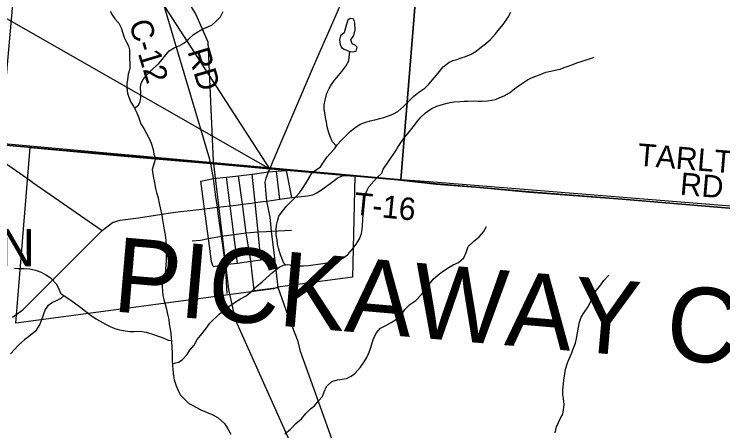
# Model space of a CAD drawing. Extents: x 0 to 42.5, y 0 to 22.
# Drawn here: x 6.916 to 7.815, y 18.353 to 18.882 of the extents above; entities that cross this region are included whole.
import ezdxf

# ---------------------------------------------------------------- set-up
doc = ezdxf.new("R2010")
doc.units = 0
for name, color, linetype in [('Default', 7, 'Continuous'), ('GM_X_City_Street', 7, 'Continuous'), ('GM_X_Corporation', 7, 'Continuous'), ('GM_X_Corporation_Text', 7, 'Continuous'), ('GM_X_County_Road', 7, 'Continuous'), ('GM_X_County_Road_Text', 7, 'Continuous'), ('GM_X_County_Text', 7, 'Continuous'), ('GM_X_Interchange_Ramps', 7, 'Continuous'), ('GM_X_Major_River', 7, 'Continuous'), ('GM_X_Minor_Lake', 7, 'Continuous'), ('GM_X_Minor_River', 7, 'Continuous'), ('GM_X_Rail_Line', 7, 'Continuous'), ('GM_X_Section', 7, 'Continuous'), ('GM_X_State_Route', 7, 'Continuous'), ('GM_X_Township', 7, 'Continuous'), ('GM_X_Township_Road', 7, 'Continuous'), ('GM_X_Township_Road_Text', 7, 'Continuous'), ('SH_Cut_Line', 7, 'Continuous')]:
    doc.layers.add(name, color=color, linetype=linetype)

msp = doc.modelspace()

# ---------------------------------------------------------------- linework, layer by layer
at = {"layer": 'Default'}
msp.add_lwpolyline([(6.77517, 18.95149), (7.23995, 18.68541), (6.77517, 19.405)], close=True, dxfattribs=at)
at = {"layer": 'GM_X_City_Street'}
for p, q in [((7.25283, 18.64698), (7.24854, 18.68262)), ((7.26806, 18.6492), (7.26126, 18.68366)), ((7.14132, 18.59393), (7.15185, 18.59509)), ((7.18585, 18.52716), (7.18372, 18.56352)), ((7.22001, 18.53092), (7.2505, 18.53493))]:
    msp.add_line(p, q, dxfattribs=at)
for points in [[(7.1707, 18.65631), (7.1687, 18.67345), (7.16507, 18.69211)], [(7.15243, 18.67005), (7.1687, 18.67345), (7.18511, 18.67508), (7.20034, 18.67671), (7.21779, 18.67878), (7.23843, 18.68183), (7.24854, 18.68262), (7.26126, 18.68366)], [(7.19892, 18.5658), (7.1943, 18.60232), (7.18971, 18.63869), (7.18511, 18.67508)], [(7.22001, 18.53092), (7.21591, 18.56814), (7.21005, 18.60448), (7.2052, 18.64053), (7.20034, 18.67671)], [(7.2288, 18.5699), (7.22521, 18.60536), (7.22144, 18.64266), (7.21779, 18.67878)], [(7.23627, 18.64461), (7.25283, 18.64698), (7.26806, 18.6492), (7.28773, 18.65113), (7.29445, 18.65246), (7.29879, 18.6545), (7.30436, 18.65786), (7.32118, 18.67025), (7.32597, 18.67421), (7.33339, 18.67733), (7.35046, 18.67616)], [(7.16816, 18.56169), (7.16581, 18.56785), (7.16199, 18.59702), (7.15703, 18.63493), (7.15243, 18.67005)], [(7.17501, 18.62543), (7.17343, 18.63677), (7.17106, 18.65319), (7.1707, 18.65631)], [(7.2505, 18.53493), (7.24638, 18.57195), (7.24234, 18.60636), (7.24026, 18.62405), (7.23627, 18.64461)], [(7.18372, 18.56352), (7.18369, 18.56404), (7.17853, 18.60016), (7.17501, 18.62543)], [(7.23592, 18.60598), (7.24234, 18.60636), (7.26765, 18.60783)], [(7.15185, 18.59509), (7.16199, 18.59702), (7.17853, 18.60016), (7.1943, 18.60232), (7.21005, 18.60448), (7.22521, 18.60536), (7.23592, 18.60598)], [(7.18645, 18.56436), (7.19892, 18.5658), (7.21591, 18.56814), (7.2288, 18.5699), (7.24638, 18.57195)], [(7.16816, 18.56169), (7.18369, 18.56404), (7.18645, 18.56436)]]:
    msp.add_lwpolyline(points, dxfattribs=at)
at = {"layer": 'GM_X_Corporation'}
msp.add_lwpolyline([(6.93599, 18.7127), (7.05994, 18.70145), (7.21478, 18.68809), (7.34783, 18.67645), (7.34506, 18.54795), (7.25039, 18.53519), (7.24478, 18.53335), (6.9177, 18.48933)], close=True, dxfattribs=at)
at = {"layer": 'GM_X_County_Road'}
msp.add_line((6.93943, 18.66839), (7.02735, 18.60733), dxfattribs=at)
for points in [[(7.16507, 18.69211), (7.16371, 18.69747), (7.15108, 18.74032), (7.12072, 18.84281), (7.0876, 18.95511)], [(6.86201, 18.71925), (6.87353, 18.71414), (6.93663, 18.67033), (6.93943, 18.66839)], [(7.3211, 18.33541), (7.29585, 18.40643), (7.27902, 18.4534), (7.27596, 18.46637), (7.2633, 18.49884), (7.2505, 18.53493)]]:
    msp.add_lwpolyline(points, dxfattribs=at)
at = {"layer": 'GM_X_Interchange_Ramps'}
msp.add_lwpolyline([(6.42536, 18.76104), (6.65154, 18.73968), (6.84834, 18.72185), (6.86191, 18.71951), (7.16496, 18.69237), (7.23984, 18.68568), (7.26115, 18.68392), (7.33328, 18.6776), (7.35035, 18.67643), (7.40226, 18.67187), (7.45109, 18.6665), (7.50672, 18.66195), (7.56903, 18.65618), (7.68737, 18.6472), (7.92905, 18.62689)], dxfattribs=at)
at = {"layer": 'GM_X_Major_River'}
for points in [[(7.0375, 18.88604), (7.03993, 18.88128), (7.04351, 18.87633), (7.04821, 18.87061), (7.05121, 18.86452), (7.05402, 18.85672), (7.05569, 18.85139), (7.05832, 18.84663), (7.06076, 18.84187), (7.06206, 18.83693), (7.06183, 18.83029), (7.062, 18.82554), (7.06234, 18.81946), (7.06231, 18.81243), (7.06038, 18.80579), (7.0592, 18.79877), (7.05842, 18.79403), (7.05858, 18.78814), (7.0593, 18.78168), (7.06117, 18.77673), (7.0636, 18.77045), (7.06754, 18.76417), (7.0713, 18.75693), (7.07372, 18.75046), (7.07634, 18.74286), (7.0801, 18.73676), (7.08366, 18.73067), (7.08647, 18.72477), (7.08947, 18.7183), (7.09208, 18.71031), (7.093, 18.70442), (7.09478, 18.69861)], [(7.09475, 18.69889), (7.09083, 18.68476), (7.09158, 18.67944), (7.09234, 18.67392), (7.09347, 18.66783), (7.09499, 18.66042), (7.09631, 18.65547), (7.09821, 18.64862), (7.09916, 18.64386), (7.10067, 18.63606), (7.10276, 18.62693), (7.1037, 18.62084), (7.10445, 18.61552), (7.10597, 18.60791), (7.1071, 18.60163), (7.10785, 18.5946), (7.10841, 18.58624), (7.10878, 18.58054), (7.10857, 18.57484), (7.10837, 18.56876), (7.10798, 18.56345), (7.10758, 18.55851), (7.107, 18.55225), (7.10545, 18.54656), (7.10391, 18.54144), (7.10352, 18.53594), (7.1037, 18.53024), (7.10426, 18.52472), (7.1054, 18.51978), (7.1073, 18.51387), (7.10881, 18.50741), (7.11033, 18.50094), (7.11165, 18.49428), (7.11241, 18.48857), (7.11354, 18.48192), (7.11429, 18.47659), (7.11466, 18.47146), (7.11523, 18.46614), (7.11579, 18.45949), (7.11615, 18.45132), (7.11613, 18.44258), (7.1165, 18.43574), (7.11706, 18.43061), (7.11781, 18.42243), (7.11876, 18.41749), (7.12104, 18.41006), (7.12389, 18.40415), (7.12675, 18.39786), (7.1319, 18.39289), (7.13725, 18.38753), (7.14221, 18.38503), (7.15253, 18.37963), (7.15769, 18.3775), (7.16763, 18.37306), (7.1745, 18.3694), (7.18233, 18.36213), (7.18671, 18.35526), (7.19052, 18.34839)]]:
    msp.add_lwpolyline(points, dxfattribs=at)
at = {"layer": 'GM_X_Minor_Lake'}
for points in [[(7.34036, 18.83512), (7.34471, 18.83431), (7.34965, 18.8352), (7.35084, 18.84013), (7.34859, 18.84244), (7.34444, 18.84419), (7.34299, 18.84953), (7.34665, 18.855), (7.34825, 18.8622), (7.34778, 18.87057), (7.34652, 18.87571), (7.34178, 18.87653), (7.33911, 18.87466), (7.33675, 18.86765), (7.33456, 18.85855), (7.32977, 18.85442), (7.32839, 18.8495), (7.32927, 18.8436), (7.33112, 18.83959), (7.33432, 18.83765)], [(7.33432, 18.83765), (7.34036, 18.83512)]]:
    msp.add_lwpolyline(points, dxfattribs=at)
at = {"layer": 'GM_X_Minor_River'}
for points in [[(7.06838, 18.76255), (7.07318, 18.76641), (7.07551, 18.77132), (7.07652, 18.77625), (7.0764, 18.78271), (7.07609, 18.78823), (7.07634, 18.79374), (7.07944, 18.79921), (7.08464, 18.806), (7.09135, 18.81257), (7.09882, 18.81914), (7.10343, 18.8246), (7.10824, 18.83044), (7.11247, 18.83533), (7.11877, 18.83945), (7.12487, 18.84166), (7.13097, 18.8452), (7.13672, 18.85046), (7.14304, 18.85609), (7.14877, 18.85964), (7.15545, 18.86356), (7.16155, 18.86596), (7.1667, 18.86837), (7.17168, 18.87269), (7.17762, 18.8787), (7.18092, 18.88532)], [(7.29355, 18.6811), (7.30414, 18.68825), (7.30915, 18.69522), (7.31263, 18.7007), (7.31686, 18.70559), (7.32204, 18.71085), (7.32609, 18.7167), (7.3305, 18.72178), (7.33626, 18.72723), (7.3424, 18.73362), (7.34794, 18.73774), (7.35482, 18.74223), (7.36187, 18.74481), (7.36719, 18.74646), (7.37309, 18.74792), (7.37974, 18.74956), (7.3845, 18.75083), (7.39078, 18.75285), (7.39592, 18.75489), (7.4026, 18.75843), (7.41007, 18.765), (7.41659, 18.77138), (7.42292, 18.77778), (7.42924, 18.78303), (7.43688, 18.78826), (7.44186, 18.79296), (7.44917, 18.80162), (7.45379, 18.80727), (7.46013, 18.81499), (7.46722, 18.8208), (7.47217, 18.82303), (7.47731, 18.82468), (7.48283, 18.82671), (7.48835, 18.82836), (7.49559, 18.83133), (7.5017, 18.83506), (7.50859, 18.84049), (7.51356, 18.84443), (7.52026, 18.84987), (7.52641, 18.85721), (7.5316, 18.86342), (7.53603, 18.86908), (7.54239, 18.87813), (7.54588, 18.88455)], [(7.32454, 18.71447), (7.31949, 18.71981), (7.31653, 18.7265), (7.31488, 18.73126), (7.31288, 18.73889), (7.31182, 18.74498), (7.31074, 18.75069), (7.30968, 18.75659), (7.30879, 18.76155), (7.30885, 18.76687), (7.31024, 18.77274), (7.31243, 18.78165), (7.31553, 18.7875), (7.31844, 18.7926), (7.3221, 18.79826), (7.32729, 18.80429), (7.33152, 18.80918), (7.33653, 18.81616), (7.3404, 18.82276), (7.34163, 18.83488)], [(7.37568, 18.67408), (7.38197, 18.68017), (7.38373, 18.6851), (7.38875, 18.69245), (7.39337, 18.69867), (7.39916, 18.70735), (7.40245, 18.71301), (7.40573, 18.71811), (7.41151, 18.72603), (7.41709, 18.733), (7.42209, 18.73902), (7.42748, 18.74599), (7.43171, 18.75108), (7.43765, 18.75671), (7.44492, 18.76195), (7.45197, 18.7653), (7.4573, 18.76695), (7.46338, 18.7684), (7.46871, 18.77005), (7.47384, 18.77076), (7.48105, 18.77125), (7.48655, 18.77157), (7.49129, 18.77171), (7.49793, 18.77182), (7.50437, 18.77156), (7.50949, 18.7717), (7.51632, 18.77219), (7.52164, 18.7727), (7.52658, 18.77379), (7.53211, 18.7762), (7.53763, 18.77842), (7.54412, 18.78234), (7.55273, 18.78908), (7.55961, 18.79376), (7.56687, 18.79881), (7.57221, 18.80103), (7.57755, 18.80344), (7.58459, 18.80584), (7.59011, 18.80825), (7.59677, 18.80969), (7.60228, 18.81077), (7.60836, 18.81242), (7.61369, 18.81426), (7.61978, 18.81628), (7.62473, 18.81813), (7.62969, 18.82016), (7.63654, 18.82256), (7.64149, 18.82403), (7.64682, 18.82568), (7.65157, 18.82734)], [(7.25995, 18.56366), (7.25793, 18.56577), (7.25375, 18.57625), (7.2509, 18.58482), (7.24976, 18.58996), (7.2492, 18.59528), (7.24806, 18.60118), (7.24808, 18.60764), (7.24866, 18.61409), (7.24982, 18.61902), (7.25156, 18.62528), (7.25616, 18.63189), (7.26134, 18.63812), (7.26709, 18.64397), (7.27284, 18.65), (7.27763, 18.65529), (7.28147, 18.66077), (7.28627, 18.66795), (7.29363, 18.6811)], [(7.11638, 18.43803), (7.11918, 18.43876), (7.12397, 18.44005), (7.12895, 18.44306), (7.13508, 18.44966), (7.13854, 18.45514), (7.14391, 18.46175), (7.14794, 18.46875), (7.15216, 18.47404), (7.15868, 18.48235), (7.16386, 18.48934), (7.17613, 18.50141), (7.18168, 18.50574), (7.18819, 18.51063), (7.1949, 18.51552), (7.20275, 18.52059), (7.20984, 18.52415), (7.21769, 18.53055), (7.22306, 18.53621), (7.23034, 18.54223), (7.23551, 18.54675), (7.24337, 18.55372), (7.2518, 18.56069), (7.25755, 18.56331), (7.26252, 18.56403), (7.26845, 18.56304), (7.27533, 18.56223), (7.28279, 18.56217), (7.28929, 18.5627), (7.29503, 18.56342), (7.30116, 18.56432), (7.30747, 18.56523), (7.31723, 18.56686), (7.32259, 18.56796), (7.32737, 18.56964), (7.33254, 18.57226), (7.33848, 18.5764), (7.34461, 18.583), (7.34979, 18.5898), (7.35363, 18.5968), (7.35652, 18.60362), (7.3571, 18.60855), (7.35749, 18.61368), (7.35808, 18.62127), (7.35848, 18.62754), (7.35868, 18.63323), (7.35869, 18.63817), (7.35928, 18.64406), (7.36044, 18.65146), (7.36294, 18.65771), (7.36563, 18.66263), (7.37558, 18.67389)], [(7.259, 18.34903), (7.26628, 18.35506), (7.27299, 18.36204), (7.28008, 18.36807), (7.28583, 18.37486), (7.29177, 18.38052), (7.29656, 18.38447), (7.30212, 18.39146), (7.30673, 18.39636), (7.30884, 18.40243), (7.31192, 18.40905), (7.31882, 18.41546), (7.3259, 18.41769), (7.33202, 18.41859), (7.33719, 18.41932), (7.34312, 18.42231), (7.3481, 18.42569), (7.3552, 18.43381), (7.35961, 18.44024), (7.36325, 18.44572), (7.36595, 18.45273), (7.36806, 18.4586), (7.36999, 18.46448), (7.37153, 18.46959), (7.37499, 18.47679), (7.38036, 18.48321), (7.38706, 18.48658), (7.39395, 18.49032), (7.402, 18.49539), (7.40813, 18.50162), (7.41139, 18.50672), (7.41753, 18.51333), (7.42538, 18.5184), (7.43209, 18.52538), (7.43727, 18.53142), (7.44264, 18.53898), (7.44724, 18.54521), (7.45376, 18.55105), (7.46046, 18.55613), (7.46774, 18.56064), (7.47291, 18.56345), (7.47942, 18.56644), (7.48632, 18.57247), (7.4892, 18.5791), (7.4917, 18.58706), (7.4986, 18.59328), (7.50588, 18.5993), (7.51125, 18.60553), (7.51509, 18.61215)], [(7.11513, 18.46702), (7.1114, 18.46731), (7.1051, 18.47039), (7.09994, 18.47233), (7.0942, 18.47408), (7.08331, 18.47758), (7.0749, 18.47897), (7.06801, 18.47864), (7.06246, 18.47868), (7.05634, 18.47948), (7.04946, 18.48067), (7.04392, 18.48242), (7.0378, 18.48494), (7.03188, 18.48764), (7.025, 18.49149), (7.01965, 18.49476), (7.01259, 18.49937), (7.0059, 18.50435), (6.99998, 18.50915), (6.99216, 18.51509), (6.98604, 18.51932), (6.97535, 18.52642), (6.97173, 18.53424), (6.96945, 18.53919), (6.96277, 18.5457), (6.95627, 18.5503), (6.95016, 18.55377), (6.94443, 18.5559), (6.93563, 18.55805), (6.92817, 18.55849), (6.92052, 18.55873), (6.91555, 18.55877)], [(7.60213, 18.35015), (7.60368, 18.35792), (7.60637, 18.36322), (7.60886, 18.3689), (7.61174, 18.37401), (7.6129, 18.37951), (7.61349, 18.38615), (7.61255, 18.39395), (7.61199, 18.39889), (7.612, 18.40383), (7.61318, 18.41712), (7.61434, 18.42509), (7.61531, 18.43097), (7.61762, 18.43931), (7.61974, 18.44442), (7.62339, 18.4518), (7.62512, 18.45711), (7.628, 18.46431), (7.62936, 18.47019), (7.63033, 18.47721), (7.63187, 18.4846), (7.63323, 18.49086), (7.63534, 18.49712), (7.6388, 18.50317), (7.64379, 18.50978), (7.64705, 18.51622), (7.64974, 18.52322), (7.65416, 18.53117), (7.65895, 18.53664), (7.66394, 18.54383), (7.67008, 18.55043)], [(6.97878, 18.52414), (6.97476, 18.52073), (6.96883, 18.51792), (6.96404, 18.51587), (6.9581, 18.51173), (6.95503, 18.50681), (6.95253, 18.49961), (6.94965, 18.49242), (6.94772, 18.48749), (6.94273, 18.47936), (6.93392, 18.47202), (6.92913, 18.46863), (6.92127, 18.46147), (6.91648, 18.45638), (6.91111, 18.45072)]]:
    msp.add_lwpolyline(points, dxfattribs=at)
at = {"layer": 'GM_X_Rail_Line'}
for points in [[(6.93446, 19.48033), (6.95529, 19.40509), (7.06565, 19.02428), (7.09443, 18.96319), (7.12266, 18.92015), (7.14624, 18.88148), (7.16122, 18.84711), (7.16795, 18.69518)], [(7.16795, 18.69518), (7.18749, 18.53209), (7.19593, 18.49415), (7.38905, 18.06269), (7.41372, 18.0008), (7.43212, 17.9111), (7.47197, 17.65619), (7.56463, 17.14484), (7.58341, 17.04913), (7.60553, 16.97375), (7.61971, 16.94218), (7.74723, 16.71174), (7.7666, 16.68172), (7.79639, 16.63739), (7.93488, 16.50931), (7.97601, 16.46994), (7.98854, 16.45646), (7.99258, 16.44438), (7.9907, 16.42806), (7.98347, 16.32444), (7.94829, 15.9349)]]:
    msp.add_lwpolyline(points, dxfattribs=at)
at = {"layer": 'GM_X_Section'}
for points in [[(6.94317, 19.22409), (7.44741, 19.17728), (7.40642, 18.67181), (6.9401, 18.71384), (6.89806, 18.71772)], [(7.44741, 19.17728), (7.95504, 19.13799), (7.91366, 18.63105), (7.44206, 18.66911), (7.40642, 18.67181)]]:
    msp.add_lwpolyline(points, close=True, dxfattribs=at)
at = {"layer": 'GM_X_State_Route'}
msp.add_line((7.08698, 18.62555), (7.11096, 18.62915), dxfattribs=at)
for points in [[(7.24005, 18.68566), (7.25313, 18.71656), (7.29156, 18.80651), (7.30112, 18.82834), (7.31392, 18.85794), (7.34504, 18.92911)], [(7.23395, 18.66809), (7.2339, 18.66857), (7.23553, 18.67389), (7.23843, 18.68183)], [(7.23843, 18.68183), (7.23995, 18.68541), (7.24003, 18.68559)], [(7.23101, 18.64392), (7.23627, 18.64461), (7.23538, 18.65378), (7.23395, 18.66809)], [(7.2166, 18.64202), (7.22144, 18.64266), (7.23101, 18.64392)], [(7.13494, 18.63244), (7.15703, 18.63493), (7.17343, 18.63677), (7.18971, 18.63869), (7.19745, 18.63961)], [(7.19745, 18.63961), (7.2052, 18.64053), (7.20596, 18.64062), (7.2166, 18.64202)], [(7.11096, 18.62915), (7.12678, 18.63152), (7.13494, 18.63244)], [(6.91343, 18.49734), (6.92641, 18.5066), (7.02735, 18.60733), (7.04029, 18.61725), (7.04989, 18.62028), (7.07355, 18.62353), (7.08698, 18.62555)]]:
    msp.add_lwpolyline(points, dxfattribs=at)
at = {"layer": 'GM_X_Township'}
msp.add_lwpolyline([(6.42536, 18.76104), (6.65154, 18.73968), (6.84834, 18.72185), (6.86191, 18.71951), (7.16496, 18.69237), (7.23984, 18.68568), (7.26115, 18.68392), (7.33328, 18.6776), (7.35035, 18.67643), (7.40226, 18.67187), (7.45109, 18.6665), (7.50672, 18.66195), (7.56903, 18.65618), (7.68737, 18.6472), (7.92905, 18.62689)], dxfattribs=at)
at = {"layer": 'GM_X_Township_Road'}
msp.add_lwpolyline([(7.35046, 18.67616), (7.40237, 18.67161), (7.4512, 18.66623), (7.50683, 18.66169), (7.56914, 18.65591), (7.68748, 18.64693), (7.92916, 18.62662)], dxfattribs=at)
at = {"layer": 'SH_Cut_Line'}
for points in [[(7.92905, 18.62689), (7.68737, 18.6472), (7.56903, 18.65618), (7.50672, 18.66195), (7.45109, 18.6665), (7.40226, 18.67187), (7.35035, 18.67643), (7.33328, 18.6776), (7.26115, 18.68392), (7.23984, 18.68568), (7.16496, 18.69237), (6.86191, 18.71951), (6.84834, 18.72185), (6.65154, 18.73968), (6.42536, 18.76104)], [(6.42536, 18.76104), (6.65154, 18.73968), (6.84834, 18.72185), (6.86191, 18.71951), (7.16496, 18.69237), (7.23984, 18.68568), (7.26115, 18.68392), (7.33328, 18.6776), (7.35035, 18.67643), (7.40226, 18.67187), (7.45109, 18.6665), (7.50672, 18.66195), (7.56903, 18.65618), (7.68737, 18.6472), (7.92905, 18.62689)]]:
    msp.add_lwpolyline(points, dxfattribs=at)

# ---------------------------------------------------------------- texts
at = {"layer": 'GM_X_Corporation_Text'}
for p in [(6.64659, 18.56174), (6.64661, 18.56155)]:
    msp.add_text('TARLTON', height=0.047348, rotation=0.00001, dxfattribs=at).set_placement(p)
at = {"layer": 'GM_X_County_Road_Text'}
for s, rotation, p in [('C-12', 286.69938, (7.06097, 18.87083)), ('RD', 286.55752, (7.13513, 18.83484))]:
    msp.add_text(s, height=0.028409, rotation=rotation, dxfattribs=at).set_placement(p)
at = {"layer": 'GM_X_County_Text'}
msp.add_text('PICKAWAY COUNTY', height=0.094697, rotation=355.0676, dxfattribs=at).set_placement((7.03919, 18.50468))
at = {"layer": 'GM_X_Township_Road_Text'}
for s, rotation, p in [('TARLTON', 355.28503, (7.70598, 18.68977)), ('RD', 355.07376, (7.75985, 18.65279)), ('T-16', 354.32516, (7.34588, 18.62761)), ('T-16', 354.32503, (7.3459, 18.62743))]:
    msp.add_text(s, height=0.028409, rotation=rotation, dxfattribs=at).set_placement(p)

doc.saveas('drawing.dxf')
